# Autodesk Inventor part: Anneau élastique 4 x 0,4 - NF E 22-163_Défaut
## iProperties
Shininess: 64.0
Length Units: 11269
Angle Units: 11279
Time Units: 11290
Mass Units: 11283
Length Display Precision: 3
Angle Display Precision: 2
Compacted: True
Part Number: Anneau élastique 4 x 0,4 - NF E 22-163_Défaut
Document SubType Name: Modeling
Created: 2006-01
Material: Par défaut
Designer: riri
Density: 0.0
Volumn: 0.0
Area: 0.0
PropertySet Name: Model Information
Control State: 0
Master: False
Checked Out: False
Author: riri
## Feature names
1. Base1
